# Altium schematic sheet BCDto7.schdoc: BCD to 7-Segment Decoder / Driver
size B; Organization: Altium Limited; Address1: L3, 12a Rodborough Rd; Address2: Frenchs Forest; Address3: NSW; Address4: Australia 2086; DocumentNumber: 1; SheetNumber: 1; SheetTotal: 1
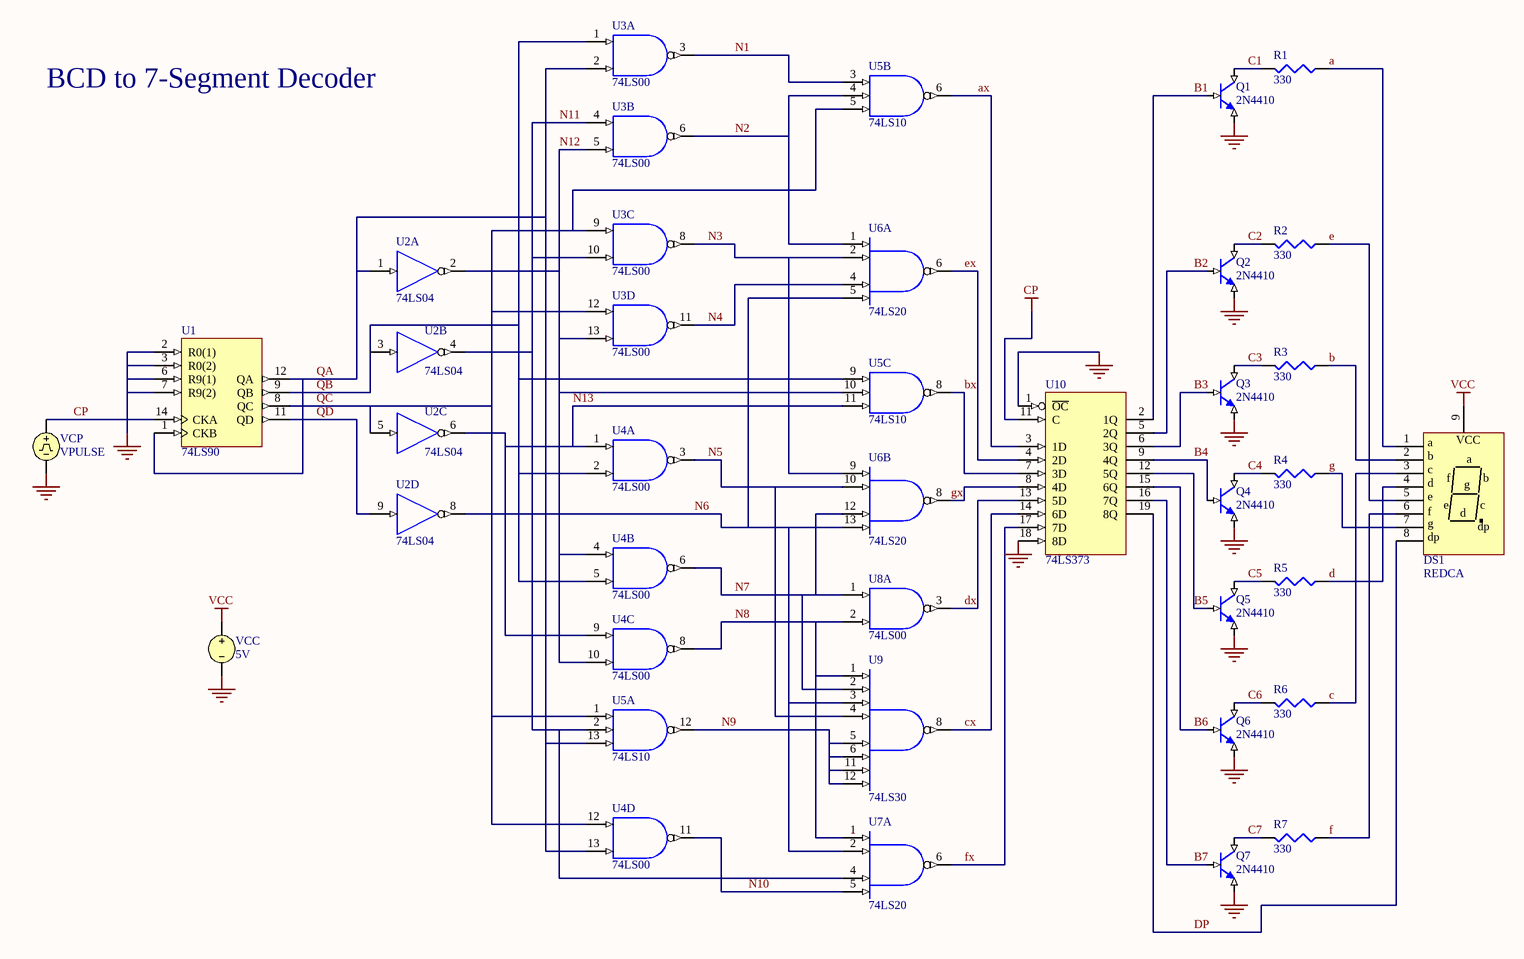
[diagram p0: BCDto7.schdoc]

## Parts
DS1  REDCA
Q1  2N4410
Q2  2N4410
Q3  2N4410
Q4  2N4410
Q5  2N4410
Q6  2N4410
Q7  2N4410
R1  330
R2  330
R3  330
R4  330
R5  330
R6  330
R7  330
U1  74LS90
U2  74LS04  (parts A,B,C,D of 6)
U3  74LS00  (parts A,B,C,D of 4)
U4  74LS00  (parts A,B,C,D of 4)
U5  74LS10  (parts A,B,C of 3)
U6  74LS20  (parts A,B of 2)
U7  74LS20  (part A of 2)
U8  74LS00  (part A of 4)
U9  74LS30
U10  74LS373
VCC  5V
VCP  VPULSE

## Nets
CP: U1.14(CKA) U10.11(C) VCP.1
GND: Q1.3(E) Q2.3(E) Q3.3(E) Q4.3(E) Q5.3(E) Q6.3(E) Q7.3(E) U1.2(R0(1)) U1.3(R0(2)) U1.6(R9(1)) U1.7(R9(2)) U1.10(GND) U2.7(GND) U3.7(GND) U4.7(GND) U5.7(GND) U6.7(GND) U7.7(GND) U8.7(GND) U9.7(GND) U10.1(~{OC}) U10.10(GND) U10.18(8D) VCC.2 VCP.2
VCC: DS1.9(VCC) U1.5(VCC) U2.14(VCC) U3.14(VCC) U4.14(VCC) U5.14(VCC) U6.14(VCC) U7.14(VCC) U8.14(VCC) U9.14(VCC) U10.20(VCC) VCC.1
a: DS1.1(a) R1.2(BOT)
ax: U5.6(Y) U10.3(1D)
b: DS1.2(b) R3.2(BOT)
B1: Q1.2(B) U10.2(1Q)
B2: Q2.2(B) U10.5(2Q)
B3: Q3.2(B) U10.6(3Q)
B4: Q4.2(B) U10.9(4Q)
B5: Q5.2(B) U10.12(5Q)
B6: Q6.2(B) U10.15(6Q)
B7: Q7.2(B) U10.16(7Q)
bx: U5.8(Y) U10.7(3D)
c: DS1.3(c) R6.2(BOT)
C1: Q1.1(C) R1.1(TOP)
C2: Q2.1(C) R2.1(TOP)
C3: Q3.1(C) R3.1(TOP)
C4: Q4.1(C) R4.1(TOP)
C5: Q5.1(C) R5.1(TOP)
C6: Q6.1(C) R6.1(TOP)
C7: Q7.1(C) R7.1(TOP)
cx: U9.8(Y) U10.14(6D)
d: DS1.4(d) R5.2(BOT)
DP: DS1.8(dp) U10.19(8Q)
dx: U8.3(Y) U10.13(5D)
e: DS1.5(e) R2.2(BOT)
ex: U6.6(Y) U10.4(2D)
f: DS1.6(f) R7.2(BOT)
fx: U7.6(Y) U10.17(7D)
g: DS1.7(g) R4.2(BOT)
gx: U6.8(Y) U10.8(4D)
N1: U3.3(Y) U5.3(A)
N2: U3.6(Y) U5.4(B) U6.1(A)
N3: U3.8(Y) U6.2(B) U6.9(A)
N4: U3.11(Y) U6.4(C)
N5: U4.3(Y) U6.10(B) U9.4(D)
N6: U2.8(Y) U6.5(D) U6.13(D) U7.2(B) U9.3(C)
N7: U4.6(Y) U6.12(C) U8.1(A) U9.2(B)
N8: U4.8(Y) U7.1(A) U8.2(B) U9.1(A)
N9: U5.12(Y) U9.5(E) U9.6(F) U9.11(G) U9.12(H)
N10: U4.11(Y) U7.5(D)
N11: U2.4(Y) U3.4(A) U3.10(B) U5.2(B) U7.4(C)
N12: U2.2(Y) U3.5(B) U3.13(B) U4.4(A) U4.10(B) U5.10(B)
N13: U2.6(Y) U4.1(A) U4.9(A) U5.11(C)
QA: U1.1(CKB) U1.12(QA) U2.1(A) U3.2(B) U4.13(B) U5.13(C)
QB: U1.9(QB) U2.3(A) U3.1(A) U4.2(B) U4.5(B) U5.9(A)
QC: U1.8(QC) U2.5(A) U3.9(A) U3.12(A) U4.12(A) U5.1(A) U5.5(C)
QD: U1.11(QD) U2.9(A)

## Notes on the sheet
- BCD to 7-Segment Decoder

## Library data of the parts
DS1 = REDCA: Common Anode Seven-Segment Display, Right Hand Decimal
Q1-Q7 = 2N4410: NPN BJT
R1-R7 = RES: Resistor
U1 = 74LS90: Binary Counter
U2 = 74LS04: Hex Inverter
U3 U4 U8 = 74LS00: Quad 2-Input Positive-NAND Gate
U5 = 74LS10: Triple 3-Input Positive-NAND Gate
U6 U7 = 74LS20: Dual 4-Input Positive-NAND Gate
U9 = 74LS30: 8-Input Positive-NAND Gate
U10 = 74LS373: Octal D-Type Transparent Latch with 3-State Output
VCC = VSRC: Voltage Source
VCP = VPULSE: Pulse Voltage Source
